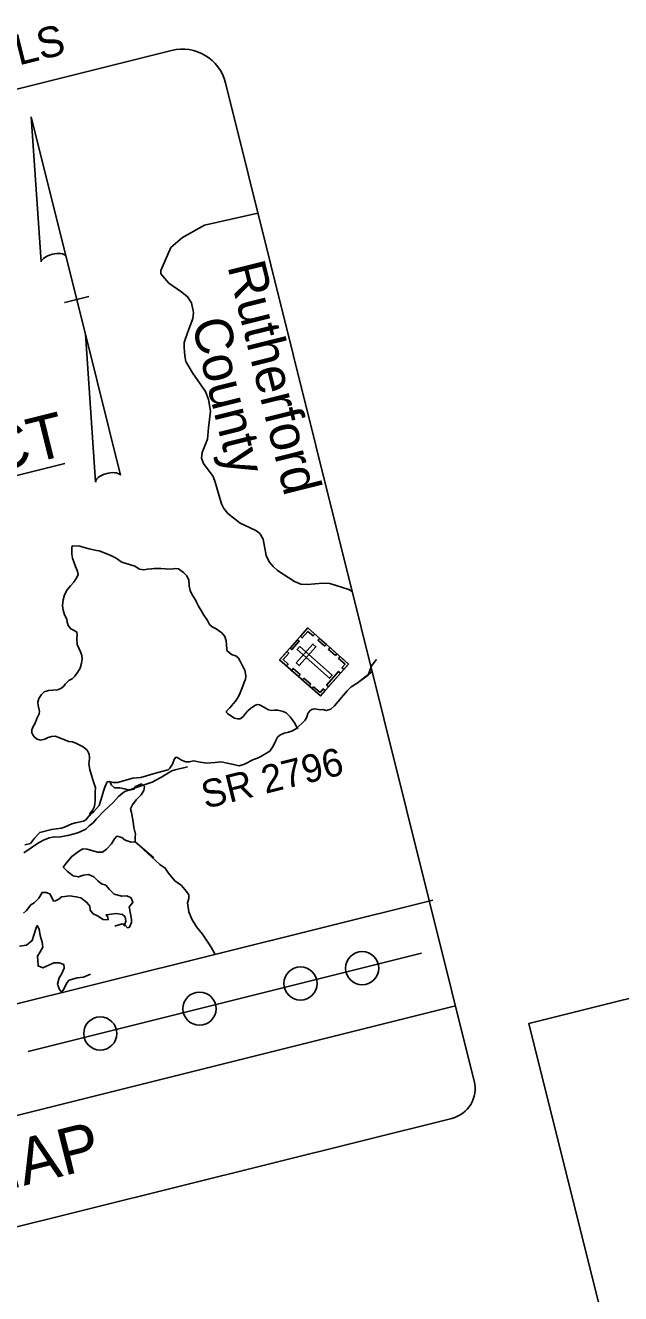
# Model space of a CAD drawing. Extents: x 1030323 to 1034123, y 654802 to 657751.
# Drawn here: x 1030807.6 to 1030952.4, y 656699.4 to 657007.6 of the extents above; entities that cross this region are included whole.
import ezdxf

# ---------------------------------------------------------------- set-up
doc = ezdxf.new("R2010")
doc.units = 0
for name, color, linetype in [('COGO Default Parcel', 7, 'Continuous'), ('Default', 7, 'Continuous'), ('Prop Dimension', 7, 'Continuous'), ('Prop Dimension Text', 7, 'Continuous'), ('Prop Grid Mask', 7, 'Continuous'), ('Prop North Arrow for Plan Sheets CELL', 7, 'Continuous'), ('Prop Shade Light', 7, 'Continuous'), ('Prop Shade Medium', 7, 'Continuous'), ('Sheet Title CELL', 7, 'Continuous')]:
    doc.layers.add(name, color=color, linetype=linetype)

msp = doc.modelspace()

# ---------------------------------------------------------------- linework, layer by layer
at = {"layer": 'COGO Default Parcel'}
msp.add_line((1030808.31, 656758.28), (1030903.98, 656782.13), dxfattribs=at)
for points in [[(1030864.2, 656961.99), (1030851.15, 656959.06), (1030845.81, 656956.05), (1030842.99, 656953.62), (1030840.61, 656948.06), (1030840.61, 656947.21), (1030842.53, 656944.98), (1030845.68, 656942.81), (1030847.09, 656941.68), (1030848.02, 656940.22), (1030848.53, 656937.88), (1030848.33, 656936.42), (1030847.02, 656932.92), (1030846.27, 656930.55), (1030846.23, 656929.31), (1030846.38, 656927.3), (1030846.64, 656925.96), (1030848.25, 656923.19), (1030851.41, 656918.69), (1030852.19, 656916.7), (1030852.62, 656913.85), (1030852.15, 656909.82), (1030851.91, 656907.09), (1030850.6, 656903.87), (1030850.45, 656902.49), (1030850.93, 656901.13), (1030853.27, 656897.98), (1030853.82, 656896.61), (1030855.34, 656891.35), (1030855.91, 656890.22), (1030856.83, 656889.04), (1030859.9, 656886.64), (1030863.64, 656884.89), (1030864.68, 656884.13), (1030865.44, 656882.77), (1030866.22, 656878.8), (1030866.88, 656877.28), (1030867.87, 656876.12), (1030868.97, 656875.12), (1030873.08, 656872.48), (1030874.58, 656871.8), (1030876.22, 656871.72), (1030879.94, 656872.08), (1030881.71, 656872.03), (1030886.32, 656870.5), (1030887.11, 656870.09)], [(1030825.56, 656818.06), (1030826.03, 656819.61), (1030826.62, 656821.5), (1030826.95, 656822.52), (1030827.16, 656823.06), (1030827.4, 656823.65), (1030827.52, 656823.83), (1030828.04, 656823.91), (1030828.99, 656823.6), (1030830, 656823.6), (1030833.75, 656824.69), (1030835.74, 656824.87), (1030837.07, 656825.27), (1030838.73, 656825.76), (1030840.19, 656826.11), (1030842.34, 656826.75), (1030842.77, 656827.16), (1030843.38, 656828.1), (1030843.83, 656829.19), (1030844.13, 656829.74), (1030844.4, 656829.77), (1030845.11, 656829.39), (1030845.63, 656829.04), (1030846.61, 656828.66), (1030847.53, 656828.65), (1030848.5, 656828.89), (1030850.15, 656828.56), (1030851.77, 656828.36), (1030853.8, 656828.48), (1030855.23, 656828.7), (1030856.73, 656828.37), (1030857.5, 656828.19), (1030859.62, 656827.72), (1030860.94, 656828.12), (1030863.08, 656829.21), (1030864.11, 656829.52), (1030864.86, 656829.94), (1030867.04, 656831.24), (1030867.93, 656832.47), (1030868.5, 656833.82), (1030868.94, 656834.64), (1030869.52, 656835.12), (1030870.59, 656835.66), (1030871.65, 656835.87), (1030872.59, 656836.22), (1030873.55, 656836.8), (1030875.59, 656838.72), (1030876.05, 656839.51), (1030876.36, 656840.38), (1030876.82, 656841.08), (1030877.27, 656841.39), (1030877.86, 656841.52), (1030879.51, 656841.31), (1030879.98, 656841.39), (1030880.85, 656841.11), (1030881.93, 656841.44), (1030882.77, 656842.31), (1030885.87, 656845.92), (1030886.86, 656846.85), (1030888.29, 656847.75), (1030891.97, 656850.6)], [(1030807.53, 656808.52), (1030808.85, 656808.83), (1030809.87, 656810.14), (1030811.13, 656811.49), (1030814.01, 656812.22), (1030816.41, 656812.53), (1030817.13, 656812.81), (1030818.93, 656813.61), (1030819.83, 656813.85), (1030821.76, 656814.28), (1030822.29, 656814.59), (1030823.35, 656815.85), (1030824.28, 656816.63), (1030825.56, 656818.06)]]:
    msp.add_lwpolyline(points, dxfattribs=at)
at = {"layer": 'Default'}
for p, q in [((1030869.47, 656853.44), (1030876.31, 656861.19)), ((1030876.31, 656861.19), (1030886.22, 656852.43)), ((1030879.37, 656844.69), (1030869.47, 656853.44)), ((1030886.22, 656852.43), (1030879.37, 656844.69)), ((1030874.97, 656848.58), (1030875.36, 656849.02)), ((1030876.65, 656847.09), (1030874.97, 656848.58)), ((1030875.36, 656849.02), (1030877.04, 656847.54)), ((1030877.04, 656847.54), (1030876.65, 656847.09))]:
    msp.add_line(p, q, dxfattribs=at)
for points in [[(1030873.86, 656836.69), (1030873.68, 656837.02), (1030873.24, 656837.89), (1030872.53, 656838.93), (1030872.01, 656839.6), (1030871.46, 656840.19), (1030871.02, 656840.58), (1030870.33, 656840.93), (1030869.67, 656841.09), (1030868.99, 656841.2), (1030868.24, 656841.18), (1030867.46, 656841.14), (1030866.79, 656841.28), (1030866.22, 656841.59), (1030865.59, 656841.94), (1030865.02, 656842.27), (1030864.58, 656842.52), (1030864.13, 656842.59), (1030863.61, 656842.4), (1030862.94, 656842.03), (1030862.35, 656841.63), (1030861.76, 656841.09), (1030861.13, 656840.41), (1030860.69, 656839.78), (1030860.02, 656839.19), (1030859.77, 656839.13), (1030859.24, 656839.08), (1030858.45, 656839.28), (1030857.84, 656839.71), (1030857.3, 656840.08), (1030856.86, 656840.34), (1030856.56, 656840.68), (1030856.56, 656840.95), (1030856.83, 656841.31), (1030857.38, 656841.8), (1030858.19, 656842.72), (1030858.75, 656843.43), (1030859.4, 656844.4), (1030859.87, 656845.43), (1030860.15, 656846.21), (1030860.48, 656847.04), (1030860.76, 656847.77), (1030861.13, 656848.76), (1030861.27, 656849.36), (1030861.19, 656850.14), (1030860.97, 656850.94), (1030860.47, 656852), (1030860.05, 656852.82), (1030859.87, 656853.15), (1030859.43, 656853.88), (1030858.81, 656854.38), (1030857.92, 656854.65), (1030857.23, 656855.14), (1030856.64, 656855.74), (1030856.64, 656856.02), (1030856.55, 656857.1), (1030856.48, 656858.06), (1030856.17, 656859.11), (1030855.38, 656860.02), (1030855.14, 656860.2), (1030854.02, 656860.98), (1030853.07, 656861.47), (1030852.37, 656862.07), (1030851.94, 656863.03), (1030851.61, 656863.48), (1030850.99, 656864.32), (1030850.37, 656865.44), (1030849.72, 656866.5), (1030849.27, 656867.45), (1030849.14, 656867.69), (1030848.65, 656868.5), (1030848.13, 656869.41), (1030847.72, 656870.31), (1030847.47, 656871.4), (1030847.45, 656871.78), (1030847.37, 656872.81), (1030846.92, 656873.85), (1030846.1, 656874.68), (1030845.17, 656875.28), (1030844.83, 656875.55), (1030844.09, 656875.65), (1030843.05, 656875.48), (1030841.7, 656875.54), (1030840.53, 656875.62), (1030838.92, 656875.63), (1030838.32, 656875.53), (1030837.31, 656875.52), (1030836.46, 656875.31), (1030835.41, 656875.51), (1030834.21, 656876.2), (1030832.92, 656876.65), (1030831.33, 656877.1), (1030830.95, 656877.24), (1030829.69, 656878.16), (1030828.4, 656878.84), (1030827.06, 656879.39), (1030825.61, 656879.93), (1030824.93, 656880.05), (1030823.15, 656880.41), (1030821.95, 656880.75), (1030820.86, 656881.06), (1030819.2, 656881.16), (1030819.1, 656881.14), (1030818.91, 656880.83), (1030818.9, 656880.01), (1030818.95, 656879.16), (1030819.1, 656878.14), (1030819.49, 656877.04), (1030819.84, 656876.11), (1030820.22, 656875.13), (1030820.27, 656874.92), (1030820.48, 656874.22), (1030820.24, 656873.59), (1030819.43, 656872.33), (1030818.62, 656871.45), (1030817.75, 656870.43), (1030817.16, 656869.26), (1030816.8, 656868.03), (1030816.66, 656866.66), (1030816.78, 656865.49), (1030817.16, 656864.35), (1030817.71, 656863.33), (1030817.77, 656862.62), (1030818.01, 656861.77), (1030818.67, 656860.98), (1030819.47, 656860.59), (1030820.18, 656860.21), (1030820.24, 656859.54), (1030820.11, 656858.64), (1030820.26, 656857.17), (1030821.03, 656855.37), (1030821.35, 656854.52), (1030821.43, 656853.58), (1030821.31, 656852.61), (1030820.92, 656851.4), (1030820.3, 656850.41), (1030819.68, 656849.49), (1030819, 656848.86), (1030818.23, 656848.45), (1030817.43, 656847.72), (1030817.29, 656847.57), (1030816.87, 656847), (1030816.25, 656846.45), (1030815.41, 656846.17), (1030814.3, 656846.09), (1030813.27, 656845.98), (1030812.2, 656845.68), (1030811.54, 656845.06), (1030810.91, 656844.06), (1030810.66, 656843.18), (1030810.76, 656842.32), (1030811, 656841.27), (1030811.04, 656841), (1030810.96, 656840.35), (1030810.38, 656839.16), (1030809.97, 656838.07), (1030809.55, 656837.21), (1030809.18, 656836.44), (1030809.16, 656835.73), (1030809.41, 656835.19), (1030809.87, 656834.64), (1030810.46, 656834.17), (1030811.28, 656833.92), (1030812.37, 656834.19), (1030813.13, 656834.56), (1030813.94, 656834.78), (1030814.87, 656834.87), (1030815.77, 656834.61), (1030817.18, 656834), (1030818.23, 656833.64), (1030819.07, 656833.5), (1030820.06, 656833.08), (1030821.67, 656832.33), (1030822.63, 656831.48), (1030823.16, 656830.54), (1030823.24, 656829.68), (1030823.12, 656828.58), (1030823.05, 656828.25), (1030823.34, 656826.69), (1030823.72, 656825.41), (1030824.01, 656824.27), (1030824.37, 656823.34), (1030824.66, 656822.43), (1030824.63, 656821.28), (1030824.59, 656820.36), (1030824.57, 656819.37), (1030824.48, 656818.36), (1030824.37, 656817.66), (1030824.04, 656817.01), (1030823.7, 656816.6), (1030823.34, 656816.14), (1030823.35, 656815.78), (1030823.34, 656815.59)], [(1030825.56, 656818.06), (1030826.03, 656819.61), (1030826.62, 656821.5), (1030826.95, 656822.52), (1030827.16, 656823.06), (1030827.4, 656823.65), (1030827.52, 656823.83), (1030828.04, 656823.91), (1030828.99, 656823.6), (1030830, 656823.6), (1030833.75, 656824.69), (1030835.74, 656824.87), (1030837.07, 656825.27), (1030838.73, 656825.76), (1030840.19, 656826.11), (1030842.34, 656826.75), (1030842.77, 656827.16), (1030843.38, 656828.1), (1030843.83, 656829.19), (1030844.13, 656829.74), (1030844.4, 656829.77), (1030845.11, 656829.39), (1030845.63, 656829.04), (1030846.61, 656828.66), (1030847.53, 656828.65), (1030848.5, 656828.89), (1030850.15, 656828.56), (1030851.77, 656828.36), (1030853.8, 656828.48), (1030855.23, 656828.7), (1030856.73, 656828.37), (1030857.5, 656828.19), (1030859.62, 656827.72), (1030860.94, 656828.12), (1030863.08, 656829.21), (1030864.11, 656829.52), (1030864.86, 656829.94), (1030867.04, 656831.24), (1030867.93, 656832.47), (1030868.5, 656833.82), (1030868.94, 656834.64), (1030869.52, 656835.12), (1030870.59, 656835.66), (1030871.65, 656835.87), (1030872.59, 656836.22), (1030873.55, 656836.8), (1030875.59, 656838.72), (1030876.05, 656839.51), (1030876.36, 656840.38), (1030876.82, 656841.08), (1030877.27, 656841.39), (1030877.86, 656841.52), (1030879.51, 656841.31), (1030879.98, 656841.39), (1030880.85, 656841.11), (1030881.93, 656841.44), (1030882.77, 656842.31), (1030885.87, 656845.92), (1030886.86, 656846.85), (1030888.29, 656847.75), (1030889.51, 656848.69), (1030891.01, 656849.73), (1030891.81, 656852.03), (1030893, 656853.56)], [(1030847.03, 656827.44), (1030844.06, 656826.72), (1030843.22, 656826.47), (1030840.55, 656824.89), (1030838.47, 656823.76), (1030834.8, 656822.47), (1030831.84, 656821.47), (1030831.23, 656821.08), (1030830.25, 656820.27)], [(1030828.24, 656823.76), (1030828.54, 656822.96), (1030829.32, 656822.33), (1030830.57, 656822.31), (1030831.77, 656822.13), (1030833.01, 656821.77), (1030834.01, 656822.01), (1030834.42, 656822.65), (1030835.85, 656823.29), (1030836.58, 656822.66), (1030836.43, 656821.71), (1030835.79, 656820.64), (1030834.6, 656819.43), (1030833.71, 656818.2), (1030833.18, 656817.25), (1030833.45, 656816.36), (1030833.82, 656814.1), (1030834.02, 656812.71), (1030834.43, 656811.08)], [(1030807.26, 656806.53), (1030810.79, 656809), (1030812.03, 656809.64), (1030813.39, 656810.2), (1030814.68, 656810.44), (1030815.7, 656810.36), (1030817.93, 656810.73), (1030820.36, 656811.4), (1030822.36, 656812.28), (1030823.16, 656813.08), (1030824.08, 656813.84), (1030824.81, 656814.74), (1030826.67, 656816.67), (1030829.06, 656818.86), (1030830.25, 656820.27)], [(1030807.53, 656808.52), (1030808.85, 656808.83), (1030809.87, 656810.14), (1030811.13, 656811.49), (1030814.01, 656812.22), (1030816.41, 656812.53), (1030817.13, 656812.81), (1030818.93, 656813.61), (1030819.83, 656813.85), (1030821.76, 656814.28), (1030822.29, 656814.59), (1030823.35, 656815.85), (1030824.28, 656816.63), (1030825.56, 656818.06)], [(1030816.79, 656803.03), (1030817.61, 656804.11), (1030818.9, 656805.68), (1030820.58, 656806.84), (1030821.56, 656807.49), (1030822.66, 656807.42), (1030824.04, 656807.02), (1030825.26, 656806.73), (1030826.39, 656806.75), (1030827.33, 656807.44), (1030828.6, 656808.76), (1030829.31, 656809.93), (1030829.86, 656810.58), (1030831.08, 656810.26), (1030831.87, 656809.63), (1030833.39, 656809.12), (1030834.33, 656809.22), (1030834.34, 656810.47), (1030834.43, 656811.08)], [(1030838.88, 656805.3), (1030834.33, 656809.22), (1030840.34, 656803.72), (1030841.66, 656802.85), (1030842.45, 656801.61), (1030843.96, 656799.78), (1030845.6, 656798.6), (1030846.83, 656797.13), (1030847.36, 656796.36), (1030847.38, 656795.86)], [(1030816.79, 656803.03), (1030817.88, 656802.02), (1030819.25, 656800.99), (1030820.52, 656800.69), (1030821.8, 656801.09), (1030822.96, 656801.25), (1030824.28, 656800.74), (1030825.23, 656799.77), (1030826.13, 656799.02), (1030827.19, 656798.71), (1030828.07, 656797.64), (1030829.25, 656796.47), (1030831.1, 656796), (1030832.32, 656796.08), (1030833.34, 656795.58), (1030833.8, 656794.45), (1030832.86, 656793.42), (1030833.19, 656791.73), (1030833.4, 656790.36), (1030833.41, 656789.6), (1030832.97, 656788.52), (1030832.43, 656788.34), (1030831.79, 656789.08), (1030831.17, 656789.31), (1030829.37, 656788.69)], [(1030807.19, 656791.86), (1030807.87, 656792.51), (1030808.94, 656793.89), (1030809.76, 656794.36), (1030810.88, 656795.57), (1030811.69, 656796.93), (1030812.77, 656796.89), (1030813.67, 656796.49), (1030814.49, 656794.79), (1030814.96, 656794.86), (1030815.74, 656795.32), (1030816.4, 656795.84), (1030817.23, 656795.91), (1030818.35, 656796.06), (1030819.95, 656795.88), (1030821.08, 656795.59), (1030822.6, 656794.5), (1030823.28, 656793.56), (1030823.38, 656792.61), (1030824.08, 656791.76), (1030825.15, 656791.23), (1030826.55, 656790.38), (1030827.74, 656790.28), (1030827.71, 656790.89), (1030827.27, 656791.45), (1030828.59, 656791.64), (1030829.63, 656791.77), (1030831.24, 656791.55), (1030831.86, 656790.99), (1030832.08, 656789.94), (1030831.67, 656788.73)], [(1030847.38, 656795.86), (1030847.4, 656795.45), (1030847.09, 656794.37), (1030847.34, 656792.22), (1030848.12, 656790.45), (1030849.21, 656788.56), (1030850.67, 656786.76), (1030852.02, 656784.8), (1030852.89, 656783.43), (1030853.8, 656781.87)], [(1030806.16, 656783.88), (1030807.87, 656784.13), (1030809.24, 656785.22), (1030809.7, 656786.58), (1030810.21, 656788.3), (1030810.51, 656788.87), (1030811, 656787.97), (1030811.21, 656786.42), (1030811.74, 656784.82), (1030811.86, 656783.61), (1030811.26, 656782.48), (1030810.54, 656781.46), (1030810.62, 656780.42), (1030810.73, 656779.07), (1030811.87, 656778.6), (1030813.51, 656779.32), (1030814.55, 656779.8), (1030815.88, 656779.78), (1030816.95, 656779.42), (1030817.07, 656778.56), (1030816.42, 656777.07), (1030815.81, 656776.16), (1030815.44, 656774.6), (1030815.89, 656773.34), (1030816.45, 656772.68), (1030816.98, 656773.43), (1030817.67, 656774.94), (1030818.25, 656775.62), (1030820.19, 656776.19), (1030821.75, 656776.36), (1030823.43, 656777.09)]]:
    msp.add_lwpolyline(points, dxfattribs=at)
for points in [[(1030878, 656859.7), (1030877.61, 656859.26), (1030876.36, 656860.36), (1030874.97, 656858.79), (1030874.53, 656859.17), (1030876.32, 656861.19)], [(1030872.02, 656856.32), (1030873.8, 656858.34), (1030874.24, 656857.95), (1030872.46, 656855.93)], [(1030880.45, 656856.74), (1030878.77, 656858.23), (1030879.16, 656858.67), (1030880.84, 656857.19)], [(1030871.16, 656851.95), (1030871.55, 656852.39), (1030870.29, 656853.5), (1030871.69, 656855.08), (1030871.26, 656855.46), (1030869.47, 656853.44)], [(1030873.52, 656852.69), (1030874.25, 656852.05), (1030878.29, 656856.63), (1030877.57, 656857.27)], [(1030874.36, 656856.68), (1030873.72, 656855.95), (1030881.6, 656848.98), (1030882.25, 656849.7)], [(1030883.02, 656854.47), (1030881.33, 656855.96), (1030881.72, 656856.41), (1030883.41, 656854.92)], [(1030885.08, 656851.14), (1030884.63, 656851.54), (1030885.39, 656852.39), (1030883.82, 656853.78), (1030884.2, 656854.22), (1030886.22, 656852.43)], [(1030874.04, 656849.4), (1030872.35, 656850.89), (1030872.75, 656851.34), (1030874.43, 656849.85)], [(1030880.9, 656847.32), (1030883.82, 656850.62), (1030884.26, 656850.23), (1030881.35, 656846.93)], [(1030880.51, 656845.98), (1030880.06, 656846.37), (1030879.31, 656845.52), (1030877.73, 656846.91), (1030877.35, 656846.47), (1030879.37, 656844.69)]]:
    msp.add_lwpolyline(points, close=True, dxfattribs=at)
at = {"layer": 'Prop Dimension'}
msp.add_line((1030817.25, 656901.17), (1030753.13, 656885.18), dxfattribs=at)
at = {"layer": 'Prop North Arrow for Plan Sheets CELL'}
for p, q in [((1030809.04, 656985.42), (1030809, 656985.41)), ((1030809.04, 656985.42), (1030809, 656985.41)), ((1030811.45, 656950.2), (1030809, 656985.41)), ((1030809.04, 656985.42), (1030817.71, 656950.64)), ((1030822.21, 656932.59), (1030817.46, 656951.66)), ((1030817.71, 656950.64), (1030817.47, 656951.62)), ((1030817.23, 656940.32), (1030823.05, 656941.77)), ((1030817.2, 656940.31), (1030817.16, 656940.3)), ((1030819.78, 656940.95), (1030817.2, 656940.31)), ((1030822.21, 656932.59), (1030824.71, 656896.69)), ((1030830.78, 656898.36), (1030822.21, 656932.59))]:
    msp.add_line(p, q, dxfattribs=at)
for centre, start_param, end_param in [((1030814.55, 656950.59), 0.216388, 2.908219), ((1030827.82, 656897.34), 0.201328, 3.141593)]:
    msp.add_ellipse(centre, major_axis=(3.08, 0.75), ratio=0.461098, start_param=start_param, end_param=end_param, dxfattribs=at)
at = {"layer": 'Prop Shade Light'}
msp.add_circle((1030825.84, 656762.65), 4.03, dxfattribs=at)
at = {"layer": 'Prop Shade Medium'}
for centre in [(1030889.54, 656778.53), (1030874.54, 656774.79), (1030849.99, 656768.67), (1030825.84, 656762.65)]:
    msp.add_circle(centre, 4.03, dxfattribs=at)
at = {"layer": 'Sheet Title CELL'}
for p, q in [((1030843.2, 657001.56), (1030605.16, 656942.21)), ((1030916.78, 656751.1), (1030856.29, 656993.69)), ((1030646.87, 656730.28), (1030906.7, 656795.06)), ((1030653.23, 656704.76), (1030912.23, 656769.34)), ((1030666.87, 656681.06), (1030911.31, 656742.01))]:
    msp.add_line(p, q, dxfattribs=at)
msp.add_lwpolyline([(1030948.53, 656691.15), (1030930.1, 656765.11), (1031721.05, 656962.31), (1031730.37, 656924.93)], dxfattribs=at)
for centre, radius, start, end in [((1030845.81, 656991.08), 10.8, 14, 104), ((1030909.5, 656749.29), 7.5, 284, 14)]:
    msp.add_arc(centre, radius, start, end, dxfattribs=at)

# ---------------------------------------------------------------- texts
at = {"layer": 'Default'}
msp.add_text('SR 2796', height=6.75, rotation=14, dxfattribs=at).set_placement((1030851.39, 656817.22))
at = {"layer": 'Prop Dimension'}
msp.add_text('VICINITY MAP', height=11.25, rotation=14, dxfattribs=at).set_placement((1030729.41, 656706.2))
at = {"layer": 'Prop Dimension Text'}
msp.add_text('PROJECT ', height=10.8, rotation=14, dxfattribs=at).set_placement((1030752.81, 656887.08))
at = {"layer": 'Prop Grid Mask'}
for s, height, p in [('Rutherford ', 9.1724, (1030856.73, 656949.13)), ('County', 9.172, (1030848, 656935.45))]:
    msp.add_text(s, height=height, rotation=284, dxfattribs=at).set_placement(p)
at = {"layer": 'Sheet Title CELL'}
msp.add_text('See Sheet 1-B For CONVENTIAL SYMBOLS', height=7.4395, rotation=14, dxfattribs=at).set_placement((1030624.15, 656952.52))

doc.saveas('drawing.dxf')
